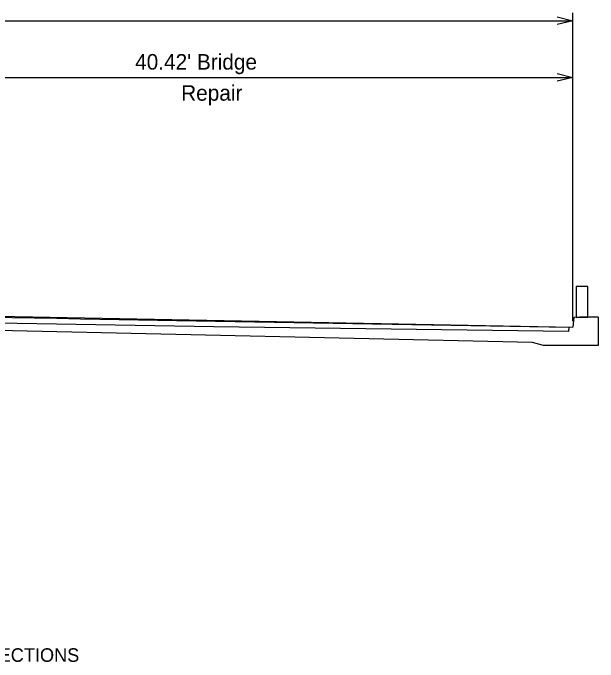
# Model space of a CAD drawing. Extents: x 10133 to 81668, y 4692 to 11018.
# Drawn here: x 29807 to 30662, y 5484 to 6432 of the extents above; entities that cross this region are included whole.
import ezdxf

# ---------------------------------------------------------------- set-up
doc = ezdxf.new("R2010")
doc.units = 0
for name, color, linetype in [('dsnStgShadingPropPav', 7, 'Continuous'), ('Level 7', 7, 'Continuous'), ('PavementRemovalStage1', 7, 'Continuous')]:
    doc.layers.add(name, color=color, linetype=linetype)

msp = doc.modelspace()

# ---------------------------------------------------------------- linework, layer by layer
at = {"layer": 'dsnStgShadingPropPav'}
msp.add_lwpolyline([(30646.82, 5988.16), (30646.82, 6032.63), (30630.16, 6032.63), (30630.16, 5987.61)], dxfattribs=at)
at = {"layer": 'Level 7'}
for p, q in [((30624.93, 5988.5), (30624.93, 6432.12)), ((28720.67, 6420.77), (30624.93, 6420.77)), ((29672.8, 6338.05), (30624.93, 6338.05)), ((30624.93, 5981.92), (30624.93, 6268.12)), ((30630.16, 5987.61), (30635.36, 5988.16)), ((30635.36, 5988.16), (30646.82, 5988.16)), ((30566.15, 5950.97), (29752.89, 5969)), ((30582.37, 5946.53), (30566.15, 5950.97))]:
    msp.add_line(p, q, dxfattribs=at)
for points in [[(30602.22, 6426.44), (30624.93, 6420.77), (30602.22, 6415.09)], [(30602.22, 6343.73), (30624.93, 6338.05), (30602.22, 6332.38)], [(30646.82, 5988.16), (30646.82, 6032.63), (30630.16, 6032.63), (30630.16, 5987.61)], [(30661.85, 5988.16), (30661.85, 5946.53), (30582.37, 5946.53)], [(30661.85, 5988.16), (30635.36, 5988.16), (30626.37, 5987.21), (30624.93, 5973.37)]]:
    msp.add_lwpolyline(points, dxfattribs=at)
at = {"layer": 'PavementRemovalStage1'}
for p, q in [((30100.93, 5973.7), (29669.91, 5981.22)), ((29752.89, 5989.91), (30624.93, 5973.37))]:
    msp.add_line(p, q, dxfattribs=at)
for points in [[(29669.92, 5985.7), (29669.95, 5989.69), (29681.97, 5989.48), (29700.48, 5989.17), (29726.48, 5988.72), (29759.21, 5988.16), (29806.37, 5987.36), (29871.61, 5986.24), (29906.06, 5985.65), (30103.23, 5982.29)], [(30103.23, 5982.29), (30619.26, 5973.47), (30618.58, 5967.18), (30100.93, 5973.7)]]:
    msp.add_lwpolyline(points, dxfattribs=at)

# ---------------------------------------------------------------- texts
at = {"layer": 'Level 7'}
for s, height, p in [("40.42' Bridge", 22.7091, (29985.85, 6349.42)), ('Repair', 22.709, (30053.08, 6304)), ('TYPICAL CONSTRUCTION SECTIONS', 19.8, (29430.57, 5484.62))]:
    msp.add_text(s, height=height, dxfattribs=at).set_placement(p)

doc.saveas('drawing.dxf')
